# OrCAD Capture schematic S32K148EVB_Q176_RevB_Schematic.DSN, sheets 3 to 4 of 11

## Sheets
3 03. S32K148 MCUs: size E; company: Freescale Semiconductor; note: SCH-29642 PDF: SPF-29642
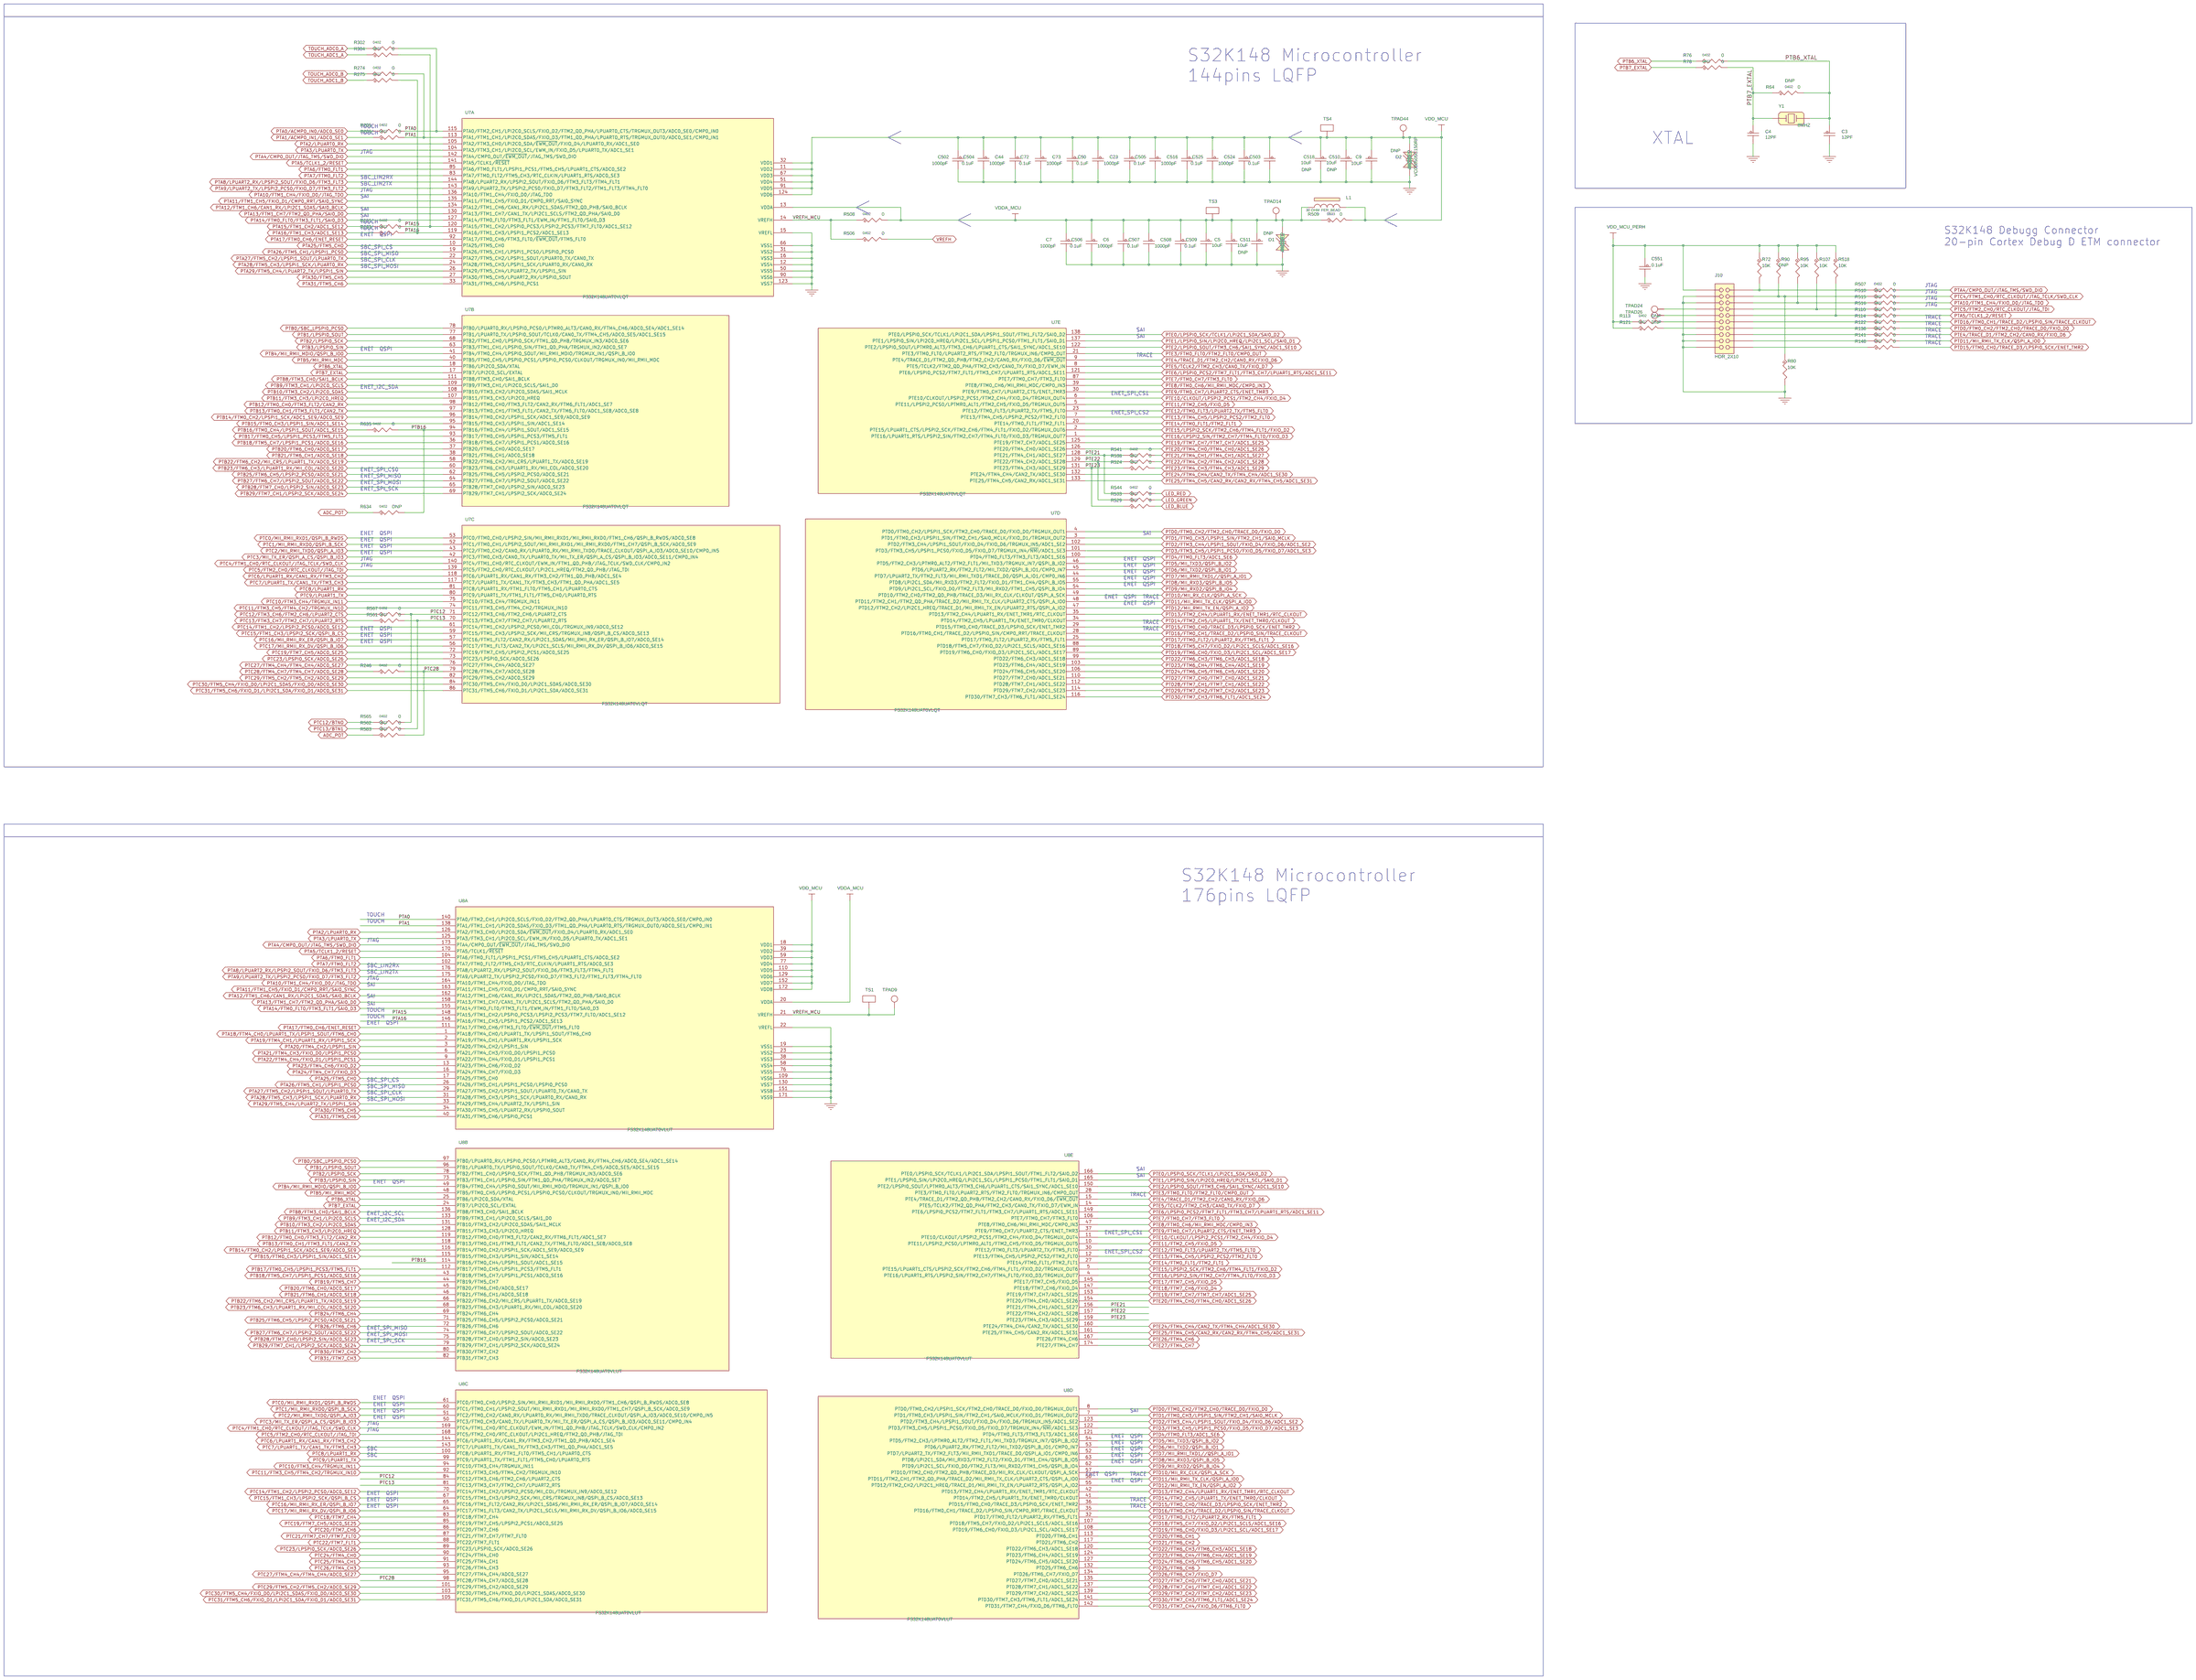
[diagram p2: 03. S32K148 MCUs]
4 04. MUXDMUX: size D; note: SCH-29642 PDF: SPF-29642
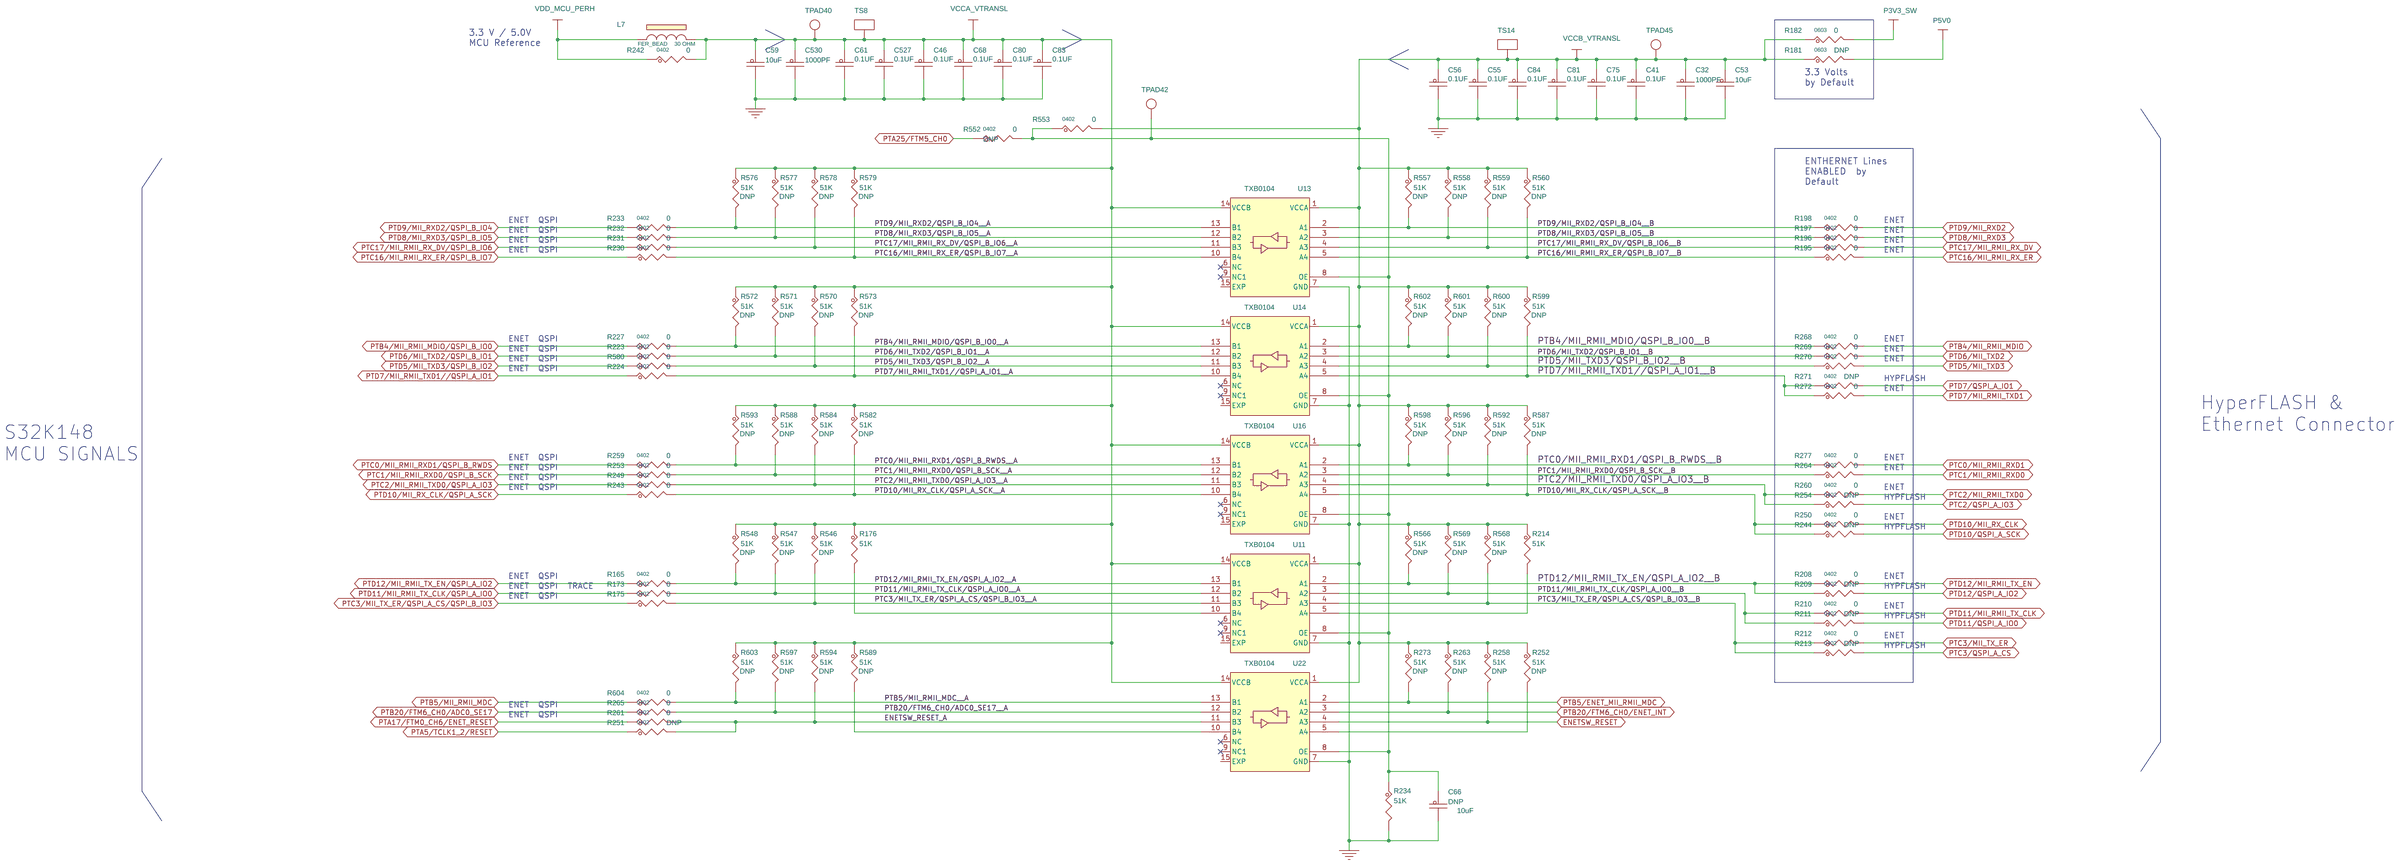
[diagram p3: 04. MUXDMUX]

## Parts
sheet 03. S32K148 MCUs
C3  12PF  [CC0402_25]
C4  12PF  [CC0402_25]
C5  10uF  [CC0603_OV]
C6  1000pF  [CC0402_25]
C7  1000pF  [CC0402_25]
C9  10UF  [CC0805_OV]
C23  1000pF  [CC0402_25]
C44  1000pF  [CC0402_25]
C50  0.1uF  [CC0402_25]
C72  0.1uF  [CC0402_25]
C73  1000pF  [CC0402_25]
C502  1000pF  [CC0402_25]
C503  0.1uF  [CC0402_25]
C504  0.1uF  [CC0402_25]
C505  0.1uF  [CC0402_25]
C506  0.1uF  [CC0402_25]
C507  0.1uF  [CC0402_25]
C508  1000pF  [CC0402_25]
C509  0.1uF  [CC0402_25]
C510  10uF  [CC0603_OV]
C511  10uF  [CC0603_OV]
C516  1000pF  [CC0402_25]
C518  10uF  [CC0603_OV]
C524  1000pF  [CC0402_25]
C525  0.1uF  [CC0402_25]
C551  0.1uF  [CC0402_25]
D1  VC080505C150RP  [0805]
D2  VC080505C150RP  [0805]
J10  HDR_2X10  [HDR210_FTSH_SM]
L1  30 OHM  [IND_0402]
R64  0  [RC0402_25]
R72  10K  [RC0603_OV]
R76  0  [RC0402_25]
R78  0  [RC0402_25]
R80  10K  [RC0603_OV]
R90  10K  [RC0603_OV]
R95  10K  [RC0603_OV]
R107  10K  [RC0603_OV]
R110  0  [RC0402_25]
R113  0  [RC0402_25]
R114  0  [RC0402_25]
R121  0  [RC0402_25]
R122  0  [RC0402_25]
R136  0  [RC0402_25]
R141  0  [RC0402_25]
R148  0  [RC0402_25]
R191  0  [RC0402_25]
R193  0  [RC0402_25]
R205  0  [RC0402_25]
R206  0  [RC0402_25]
R246  0  [RC0402_25]
R274  0  [RC0402_25]
R275  0  [RC0402_25]
R302  0  [RC0402_25]
R304  0  [RC0402_25]
R506  0  [RC0402_25]
R507  0  [RC0402_25]
R508  0  [RC0402_25]
R509  0  [RC0603]
R510  0  [RC0402_25]
R515  0  [RC0402_25]
R516  0  [RC0402_25]
R518  10K  [RC0603_OV]
R524  0  [RC0402_25]
R529  0  [RC0402_25]
R533  0  [RC0402_25]
R538  0  [RC0402_25]
R541  0  [RC0402_25]
R544  0  [RC0402_25]
R561  0  [RC0402_25]
R562  0  [RC0402_25]
R565  0  [RC0402_25]
R567  0  [RC0402_25]
R583  0  [RC0402_25]
R634  0  [RC0402_25]
R635  0  [RC0402_25]
TPAD9  TPAD_030  [TPAD_030]
TPAD14  TPAD_030  [TPAD_030]
TPAD24  TPAD_030  [TPAD_030]
TPAD26  TPAD_030  [TPAD_030]
TPAD44  TPAD_030  [TPAD_030]
TS1  TESTLOOP  [testpoint_135_070mil]
TS3  TESTLOOP  [testpoint_135_070mil]
TS4  TESTLOOP  [testpoint_135_070mil]
U7  FS32K148UAT0VLQT  [LQFP144_0P5_20X20MM]  (sections A,B,C,D,E)
U8  FS32K148UAT0VLUT  [TQFP176]  (sections A,B,C,D,E)
Y1  8MHZ  [xtal2_3p3x2p6]
sheet 04. MUXDMUX
C32  1000PF  [CC0603_OV]
C41  0.1UF  [CC0603_OV]
C46  0.1UF  [CC0603_OV]
C53  10uF  [CC0603_OV]
C55  0.1UF  [CC0603_OV]
C56  0.1UF  [CC0603_OV]
C59  10uF  [CC0603_OV]
C61  0.1UF  [CC0603_OV]
C66  10uF  [CC0603_OV]
C68  0.1UF  [CC0603_OV]
C75  0.1UF  [CC0603_OV]
C80  0.1UF  [CC0603_OV]
C81  0.1UF  [CC0603_OV]
C83  0.1UF  [CC0603_OV]
C84  0.1UF  [CC0603_OV]
C527  0.1UF  [CC0603_OV]
C530  1000PF  [CC0603_OV]
L7  30 OHM  [IND_0402]
R165  0  [RC0402_25]
R173  0  [RC0402_25]
R175  0  [RC0402_25]
R176  51K  [RC0402_25]
R181  0  [RC0603]
R182  0  [RC0603]
R195  0  [RC0402_25]
R196  0  [RC0402_25]
R197  0  [RC0402_25]
R198  0  [RC0402_25]
R208  0  [RC0402_25]
R209  0  [RC0402_25]
R210  0  [RC0402_25]
R211  0  [RC0402_25]
R212  0  [RC0402_25]
R213  0  [RC0402_25]
R214  51K  [RC0402_25]
R223  0  [RC0402_25]
R224  0  [RC0402_25]
R227  0  [RC0402_25]
R230  0  [RC0402_25]
R231  0  [RC0402_25]
R232  0  [RC0402_25]
R233  0  [RC0402_25]
R234  51K  [RC0402_25]
R242  0  [RC0402_25]
R243  0  [RC0402_25]
R244  0  [RC0402_25]
R249  0  [RC0402_25]
R250  0  [RC0402_25]
R251  0  [RC0402_25]
R252  51K  [RC0402_25]
R253  0  [RC0402_25]
R254  0  [RC0402_25]
R258  51K  [RC0402_25]
R259  0  [RC0402_25]
R260  0  [RC0402_25]
R261  0  [RC0402_25]
R263  51K  [RC0402_25]
R264  0  [RC0402_25]
R265  0  [RC0402_25]
R268  0  [RC0402_25]
R269  0  [RC0402_25]
R270  0  [RC0402_25]
R271  0  [RC0402_25]
R272  0  [RC0402_25]
R273  51K  [RC0402_25]
R277  0  [RC0402_25]
R546  51K  [RC0402_25]
R547  51K  [RC0402_25]
R548  51K  [RC0402_25]
R552  0  [RC0402_25]
R553  0  [RC0402_25]
R557  51K  [RC0402_25]
R558  51K  [RC0402_25]
R559  51K  [RC0402_25]
R560  51K  [RC0402_25]
R566  51K  [RC0402_25]
R568  51K  [RC0402_25]
R569  51K  [RC0402_25]
R570  51K  [RC0402_25]
R571  51K  [RC0402_25]
R572  51K  [RC0402_25]
R573  51K  [RC0402_25]
R576  51K  [RC0402_25]
R577  51K  [RC0402_25]
R578  51K  [RC0402_25]
R579  51K  [RC0402_25]
R580  0  [RC0402_25]
R582  51K  [RC0402_25]
R584  51K  [RC0402_25]
R587  51K  [RC0402_25]
R588  51K  [RC0402_25]
R589  51K  [RC0402_25]
R592  51K  [RC0402_25]
R593  51K  [RC0402_25]
R594  51K  [RC0402_25]
R596  51K  [RC0402_25]
R597  51K  [RC0402_25]
R598  51K  [RC0402_25]
R599  51K  [RC0402_25]
R600  51K  [RC0402_25]
R601  51K  [RC0402_25]
R602  51K  [RC0402_25]
R603  51K  [RC0402_25]
R604  0  [RC0402_25]
TPAD40  TPAD_030  [TPAD_030]
TPAD42  TPAD_030  [TPAD_030]
TPAD45  TPAD_030  [TPAD_030]
TS8  TESTLOOP  [testpoint_135_070mil]
TS14  TESTLOOP  [testpoint_135_070mil]
U11  TXB0104  [qfn14_rgy]
U13  TXB0104  [qfn14_rgy]
U14  TXB0104  [qfn14_rgy]
U16  TXB0104  [qfn14_rgy]
U22  TXB0104  [qfn14_rgy]

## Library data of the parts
C3 C4 = CAP_NP: CAP CER 12PF 50V 5% C0G 0402; AGILE_PN: 150-75680; CAD_APPROVED: Yes; FPLIST: CC0402_25,CC0402_HD,0402_CC; HEIGHT: 0.55MM; MFG_NAME01: NIC COMPONENTS CORP; MFG_PN01: NMC0402NPO120J50TRPF; ROHS: Yes; Tolerance: 5%; VOLTAGE: 50V
C5 = CAP_NP: CAP CER 10uF 25V 20% X5R 0603; AGILE_PN: 150-79272; CAD_APPROVED: Yes; FPLIST: CC0603_OV,CC0603,0603_CC; HEIGHT: 1MM; MFG_NAME01: Murata; MFG_PN01: GRM188R61E106MA73D; ROHS: Yes; TOL: 10%; Tolerance: 20%; VOLTAGE: 25V
C6 C7 C23 C44 C73 C502 C508 C516 C524 = CAP_NP: CAP CER 1000pF 50V 10% X7R AEC-Q200 0402; AGILE_PN: 150-79040; CAD_APPROVED: Yes; FPLIST: CC0402_25,CC0402_HD,0402_CC; HEIGHT: 0.55MM; MFG_NAME01: MURATA; MFG_PN01: GCM155R71H102KA37D; ROHS: Yes; Tolerance: 10%; VOLTAGE: 50V
C9 = CAP_NP: CAP CER 10UF 10V 10% X7R 0805; AGILE_PN: 150-78501; CAD_APPROVED: Yes; FPLIST: CC0603_OV,CC0603,0603_CC; HEIGHT: 1.4MM; MFG_NAME01: Murata; MFG_PN01: GRM21BR71A106KE51L; ROHS: Yes; Tolerance: 10%; VOLTAGE: 10V
C50 C72 C503-C507 C509 C525 C551 = CAP_NP: CAP CER 0.1uF 16V 10% X7R AEC-Q200 0402; AGILE_PN: 150-79025; CAD_APPROVED: Yes; FPLIST: CC0402_25,CC0402_HD,0402_CC; HEIGHT: 0.55MM; MFG_NAME01: MURATA; MFG_PN01: GCM155R71C104KA55D; ROHS: Yes
C510 C511 C518 = CAP_NP: CAP CER 10uF 25V 20% X5R 0603; AGILE_PN: 150-79272; ASSY_OPT: DNP; CAD_APPROVED: Yes; FPLIST: CC0603_OV,CC0603,0603_CC; HEIGHT: 1MM; MFG_NAME01: Murata; MFG_PN01: GRM188R61E106MA73D; ROHS: Yes; TOL: 10%; Tolerance: 20%; VOLTAGE: 25V
D1 D2 = TRANZORB_BIDIR_AA: DIODE TVS 5.6V 0.3J 18V 0805; AGILE_PN: 480-75537; ASSY_OPT: DNP; CAD_APPROVED: Yes; HEIGHT: 1.02MM; MFG_NAME01: AVX; ROHS: Yes
J10 = CONN_HDR_10X2: HDR 2X10 SMT 50MIL SP 251H AU; AGILE_PN: 211-78962; CAD_APPROVED: Yes; HEIGHT: 6.35MM; MFG_NAME01: SAMTEC; MFG_PN01: FTSH-110-01-L-DV-K; ROHS: Yes
L1 L7 = INDUCTOR_FERRITE: IND FER BEAD 30 OHM@100MHZ 2.2A 25% 0402; AGILE_PN: 180-77768; CAD_APPROVED: Yes; FPLIST: IND_0402,0402_CC; HEIGHT: 0.55MM; MFG_NAME01: Murata; MFG_PN01: BLM15PD300SN1D; PART_TYPE: FERRITE\BEAD; ROHS: Yes; Tolerance: 25%; _DESC: FER_BEAD
R64 R113 R121 R209 R211 R213 R244 R251 R254 R271 R552 R634 = RES: RES MF ZERO OHM 1/16W -- AEC-Q200 0402; AGILE_PN: 470-80742; ASSY_OPT: DNP; CAD_APPROVED: Yes; FPLIST: RC0402_25,RC0402_HD,0402_CC; HEIGHT: 0.45 MM; MFG_NAME01: VISHAY INTERTECHNOLOGY; MFG_PN01: CRCW04020000Z0ED; PCKG: 0402; ROHS: Yes
R72 R80 R95 R107 R518 = RES: RES MF 10K 1/10W 0.1% AEC-Q200 0603; AGILE_PN: 470-80764; CAD_APPROVED: Yes; FPLIST: RC0603_OV,RC0603,0603_CC; HEIGHT: 0.55MM; MFG_NAME01: Vishay Intertechnology; MFG_PN01: TNPW060310K0BEEN; ROHS: Yes; Tolerance: 0.1%
R76 R78 R110 R114 R122 R136 R141 R148 R165 R173 R175 R191 R193 R195-R198 R205 R206 R208 R210 R212 R223 R224 R227 R230-R233 R242 R243 R246 R249 R250 R253 R259-R261 R264 R265 R268-R270 R272 R274 R275 R277 R302 R304 R506-R508 R510 R515 R516 R524 R529 R533 R538 R541 R544 R553 R561 R562 R565 R567 R580 R583 R604 R635 = RES: RES MF ZERO OHM 1/16W -- AEC-Q200 0402; AGILE_PN: 470-80742; CAD_APPROVED: Yes; FPLIST: RC0402_25,RC0402_HD,0402_CC; HEIGHT: 0.45 MM; MFG_NAME01: VISHAY INTERTECHNOLOGY; MFG_PN01: CRCW04020000Z0ED; PCKG: 0402; ROHS: Yes
R90 = RES: RES MF 10K 1/10W 0.1% AEC-Q200 0603; AGILE_PN: 470-80764; ASSY_OPT: DNP; CAD_APPROVED: Yes; FPLIST: RC0603_OV,RC0603,0603_CC; HEIGHT: 0.55MM; MFG_NAME01: Vishay Intertechnology; MFG_PN01: TNPW060310K0BEEN; ROHS: Yes; Tolerance: 0.1%
R182 R509 = RES: RES MF ZERO OHM 1/10W -- AEC-Q200 0603; AGILE_PN: 470-75407; CAD_APPROVED: Yes; FPLIST: RC0603_OV,RC0603,R603-X2,0603_CC; HEIGHT: 0.6MM; MFG_NAME01: PANASONIC; MFG_PN01: ERJ-3GEY0R00V; PCKG: 0603; ROHS: Yes; Tolerance: 1%
TPAD9 TPAD14 TPAD24 TPAD26 TPAD40 TPAD42 TPAD44 TPAD45 = TestLoop: TEST POINT PAD 30MIL DIA SMT, NO PART TO ORDER; AGILE_PN: 211-76642; CAD_APPROVED: Yes; HEIGHT: 0.1MM; MFG_NAME01: NOTACOMPONENT; MFG_PN01: NOTACOMPONENT; ROHS: Yes
TS1 TS3 TS4 TS8 TS14 = TEST_POINT_4: TEST POINT PAD SIZE 3.4MM X 1.8MM SMT; AGILE_PN: 211-75906; CAD_APPROVED: Yes; HEIGHT: 1.53 MM; MFG_NAME01: KEYSTONE ELECTRONICS; MFG_PN01: 5015; PRIORITY_PN: 922-00014; ROHS: Yes
U7 = S32K1XX_LQFP_144P: IC MCU 2M FLASH 2.7-5.5V 112MHZ LQFP144; AGILE_PN: TMP-WF-28630; ASSY_OPT: DNP; CAD_APPROVED: Yes; HEIGHT: 1.6MM; MFG_NAME01: NXP SEMICONDUCTORS; MFG_PN01: PS32K148UAT0VLQT; PRE_APN: 344-02229; ROHS: Yes; Temp_Range: -40C to 125C
U8 = S32K1XX_LQFP_176P: IC MCU 32MHZ FLASH 2.7-5.5V 112MHZ LQFP176; AGILE_PN: TMP-WF-28631; CAD_APPROVED: Yes; HEIGHT: 1.6MM; MFG_NAME01: NXP SEMICONDUCTORS; MFG_PN01: PS32K118UEX0MLUT; PRE_APN: 344-02230; ROHS: Yes; Temp_Range: -40C to 125C
Y1 = XTAL_CS10: XTAL 8MHZ 8pF AEC-Q200 SMD; AGILE_PN: 230-77981; CAD_APPROVED: Yes; HEIGHT: 1MM; MFG_NAME01: NDK; MFG_PN01: NX3225GD-8MHZ-STD-CRA-3; ROHS: Yes
C32 C530 = CAP_NP: CAP CER 1000PF 25V 5% C0G CC0603; AGILE_PN: 150-75193; CAD_APPROVED: Yes; FPLIST: CC0603_OV,CC0603,0603_CC; HEIGHT: 0.87MM; MFG_NAME01: KEMET; MFG_PN01: C0603C102J3GAC; ROHS: Yes; Tolerance: 5%; VOLTAGE: 25V
C41 C46 C55 C56 C61 C68 C75 C80 C81 C83 C84 C527 = CAP_NP: CAP CER 0.10UF 25V 10% X7R 0603; AGILE_PN: 150-75016; CAD_APPROVED: Yes; FPLIST: CC0603_OV,CC0603,0603_CC; HEIGHT: 0.97 MM; MFG_NAME01: KEMET; MFG_PN01: C0603C104K3RAC; ROHS: Yes; TOL: 10%; Tolerance: 10%; VOLTAGE: 25V
C53 C59 = CAP_NP: CAP CER 10uF 25V 20% X5R 0603; AGILE_PN: 150-79272; CAD_APPROVED: Yes; FPLIST: CC0603_OV,CC0603,0603_CC; HEIGHT: 1MM; MFG_NAME01: Murata; MFG_PN01: GRM188R61E106MA73D; ROHS: Yes; SIGNAL_MODEL: DEFAULT_CAPACITOR_1e+07pF_2_1; Tolerance: 20%; VOLTAGE: 25V
C66 = CAP_NP: CAP CER 10uF 25V 20% X5R 0603; AGILE_PN: 150-79272; ASSY_OPT: DNP; CAD_APPROVED: Yes; FPLIST: CC0603_OV,CC0603,0603_CC; HEIGHT: 1MM; MFG_NAME01: Murata; MFG_PN01: GRM188R61E106MA73D; ROHS: Yes; SIGNAL_MODEL: DEFAULT_CAPACITOR_1e+07pF_2_1; Tolerance: 20%; VOLTAGE: 25V
R176 R214 R234 = RES: RES MF 51K 1/16W 1% AEC-Q200 0402; AGILE_PN: 470-80733; CAD_APPROVED: Yes; FPLIST: RC0402_25,RC0402_HD,0402_CC; HEIGHT: 0.4MM; MFG_NAME01: VISHAY INTERTECHNOLOGY; MFG_PN01: CRCW040251K0FKED; ROHS: Yes; Tolerance: 1%
R181 = RES: RES MF ZERO OHM 1/10W -- AEC-Q200 0603; AGILE_PN: 470-75407; ASSY_OPT: DNP; CAD_APPROVED: Yes; FPLIST: RC0603_OV,RC0603,R603-X2,0603_CC; HEIGHT: 0.6MM; MFG_NAME01: PANASONIC; MFG_PN01: ERJ-3GEY0R00V; PCKG: 0603; ROHS: Yes; Tolerance: 1%
R252 R258 R263 R273 R546-R548 R557-R560 R566 R568-R573 R576-R579 R582 R584 R587-R589 R592-R594 R596-R603 = RES: RES MF 51K 1/16W 1% AEC-Q200 0402; AGILE_PN: 470-80733; ASSY_OPT: DNP; CAD_APPROVED: Yes; FPLIST: RC0402_25,RC0402_HD,0402_CC; HEIGHT: 0.4MM; MFG_NAME01: VISHAY INTERTECHNOLOGY; MFG_PN01: CRCW040251K0FKED; ROHS: Yes; Tolerance: 1%
U11 U13 U14 U16 U22 = TXB0104: IC VXLTR 4BIT BIDIRECTIONAL 1.2-3.6V/1.65-5.5V QFN14; AGILE_PN: 312-78758; CAD_APPROVED: Yes; HEIGHT: 1MM; MFG_NAME01: TEXAS INSTRUMENTS; MFG_PN01: TXB0104RGYRG4; ROHS: Yes

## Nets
GND: C3.2 C4.2 C5.2 C6.2 C7.2 C9.2 C23.2 C32.2 C41.2 C44.2 C46.2 C50.2 C53.2 C55.2 C56.2 C59.2 C61.2 C66.2 C68.2 C72.2 C73.2 C75.2 C80.2 C81.2 C83.2 C84.2 C502.2 C503.2 C504.2 C505.2 C506.2 C507.2 C508.2 C509.2 C510.2 C511.2 C516.2 C518.2 C524.2 C525.2 C527.2 C530.2 C551.2 D1.2(ANODE2) D2.2(ANODE2) J10.3 J10.5 J10.15 J10.17 J10.19 R80.2 R234.2 U7.12(VSS4) U7.15(VREFL) U7.16(VSS3) U7.31(VSS2) U7.50(VSS5) U7.66(VSS1) U7.90(VSS6) U7.123(VSS7) U8.19(VSS1) U8.22(VREFL) U8.23(VSS2) U8.38(VSS3) U8.58(VSS4) U8.76(VSS5) U8.109(VSS6) U8.130(VSS7) U8.151(VSS8) U8.171(VSS9) U11.7(GND) U13.7(GND) U14.7(GND) U16.7(GND) U22.7(GND) ; also on sheet 1 2 5 6 7 8 9 11
P3V3_SW: R182.2 ; also on sheet 1 2 5 6 7 11
P5V0: R181.2 ; also on sheet 1 2 6 9 11
VCCA_VTRANSL: C46.1 C59.1 C61.1 C68.1 C80.1 C83.1 C527.1 C530.1 L7.2 R176.1 R242.2 R546.1 R547.1 R548.1 R570.1 R571.1 R572.1 R573.1 R576.1 R577.1 R578.1 R579.1 R582.1 R584.1 R588.1 R589.1 R593.1 R594.1 R597.1 R603.1 TPAD40.1(Pin1) TS8.1 U11.14(VCCB) U13.14(VCCB) U14.14(VCCB) U16.14(VCCB) U22.14(VCCB)
VCCB_VTRANSL: C32.1 C41.1 C53.1 C55.1 C56.1 C75.1 C81.1 C84.1 R181.1 R182.1 R214.1 R252.1 R258.1 R263.1 R273.1 R553.2 R557.1 R558.1 R559.1 R560.1 R566.1 R568.1 R569.1 R587.1 R592.1 R596.1 R598.1 R599.1 R600.1 R601.1 R602.1 TPAD45.1(Pin1) TS14.1 U11.1(VCCA) U13.1(VCCA) U14.1(VCCA) U16.1(VCCA) U22.1(VCCA)
VDD_MCU: C9.1 C23.1 C44.1 C50.1 C72.1 C73.1 C502.1 C503.1 C504.1 C505.1 C510.1 C516.1 C518.1 C524.1 C525.1 D2.1(ANODE1) L1.1 R509.2 TPAD44.1(Pin1) TS4.1 U7.11(VDD2) U7.32(VDD1) U7.51(VDD4) U7.67(VDD3) U7.91(VDD5) U7.124(VDD6) U8.18(VDD1) U8.39(VDD2) U8.59(VDD3) U8.77(VDD4) U8.110(VDD5) U8.129(VDD6) U8.152(VDD7) U8.172(VDD8) ; also on sheet 2
VDD_MCU_PERH: C551.1 J10.1 L7.1 R72.1 R90.1 R95.1 R107.1 R113.1 R121.1 R242.1 R518.1 ; also on sheet 2 6 9 11
VDDA_MCU: C5.1 C6.1 C7.1 C506.1 C507.1 C508.1 C509.1 C511.1 D1.1(ANODE1) L1.2 R508.2 R509.1 TPAD14.1(Pin1) TS3.1 U7.13(VDDA) U8.20(VDDA)
ADC_POT: R583.1 R634.1 ; also on sheet 9
ENETSW_RESET: R258.2 U22.4(A3) ; also on sheet 6
ENETSW_RESET_A: R251.2 R261.2 R594.2 U22.11(B3)
EXP: U11.15(EXP) U13.15(EXP) U14.15(EXP) U16.15(EXP) U22.15(EXP)
LED_BLUE: R529.2 ; also on sheet 9
LED_GREEN: R533.2 ; also on sheet 9
LED_RED: R544.2 ; also on sheet 9
PTA0: R205.2 R302.2 U7.115(PTA0/FTM2_CH1/LPI2C0_SCLS/FXIO_D2/FTM2_QD_PHA/LPUART0_CTS/TRGMUX_OUT3/ADC0_SE0/CMP0_IN0) U8.140(PTA0/FTM2_CH1/LPI2C0_SCLS/FXIO_D2/FTM2_QD_PHA/LPUART0_CTS/TRGMUX_OUT3/ADC0_SE0/CMP0_IN0)
PTA0/ACMP0_IN0/ADC0_SE0: R205.1 ; also on sheet 11
PTA1: R206.2 R274.2 U7.113(PTA1/FTM1_CH1/LPI2C0_SDAS/FXIO_D3/FTM1_QD_PHA/LPUART0_RTS/TRGMUX_OUT0/ADC0_SE1/CMP0_IN1) U8.138(PTA1/FTM1_CH1/LPI2C0_SDAS/FXIO_D3/FTM1_QD_PHA/LPUART0_RTS/TRGMUX_OUT0/ADC0_SE1/CMP0_IN1)
PTA1/ACMP0_IN1/ADC0_SE1: R206.1 ; also on sheet 11
PTA2/LPUART0_RX: U7.105(PTA2/FTM3_CH0/LPI2C0_SDA/~{EWM_OUT}/FXIO_D4/LPUART0_RX/ADC1_SE0) U8.126(PTA2/FTM3_CH0/LPI2C0_SDA/~{EWM_OUT}/FXIO_D4/LPUART0_RX/ADC1_SE0) ; also on sheet 2 11
PTA3/LPUART0_TX: U7.104(PTA3/FTM3_CH1/LPI2C0_SCL/EWM_IN/FXIO_D5/LPUART0_TX/ADC1_SE1) U8.125(PTA3/FTM3_CH1/LPI2C0_SCL/EWM_IN/FXIO_D5/LPUART0_TX/ADC1_SE1) ; also on sheet 2 11
PTA4/CMP0_OUT/JTAG_TMS/SWD_DIO: R507.2 U7.142(PTA4/CMP0_OUT/~{EWM_OUT}/JTAG_TMS/SWD_DIO) U8.173(PTA4/CMP0_OUT/~{EWM_OUT}/JTAG_TMS/SWD_DIO) ; also on sheet 5
PTA5/TCLK1_2/RESET: R110.2 R251.1 U7.141(PTA5/TCLK1/~{RESET}) U8.170(PTA5/TCLK1/~{RESET}) ; also on sheet 2 5 11
PTA6/FTM0_FLT1: U7.85(PTA6/FTM0_FLT1/LPSPI1_PCS1/FTM5_CH5/LPUART1_CTS/ADC0_SE2) U8.104(PTA6/FTM0_FLT1/LPSPI1_PCS1/FTM5_CH5/LPUART1_CTS/ADC0_SE2) ; also on sheet 11
PTA7/FTM0_FLT2: U7.83(PTA7/FTM0_FLT2/FTM5_CH3/RTC_CLKIN/LPUART1_RTS/ADC0_SE3) U8.102(PTA7/FTM0_FLT2/FTM5_CH3/RTC_CLKIN/LPUART1_RTS/ADC0_SE3) ; also on sheet 11
PTA8/LPUART2_RX/LPSPI2_SOUT/FXIO_D6/FTM3_FLT3: U7.144(PTA8/LPUART2_RX/LPSPI2_SOUT/FXIO_D6/FTM3_FLT3/FTM4_FLT1) U8.176(PTA8/LPUART2_RX/LPSPI2_SOUT/FXIO_D6/FTM3_FLT3/FTM4_FLT1) ; also on sheet 2 11
PTA9/LPUART2_TX/LPSPI2_PCS0/FXIO_D7/FTM3_FLT2: U7.143(PTA9/LPUART2_TX/LPSPI2_PCS0/FXIO_D7/FTM3_FLT2/FTM1_FLT3/FTM4_FLT0) U8.175(PTA9/LPUART2_TX/LPSPI2_PCS0/FXIO_D7/FTM3_FLT2/FTM1_FLT3/FTM4_FLT0) ; also on sheet 2 11
PTA10/FTM1_CH4/FXIO_D0/JTAG_TDO: R515.2 U7.136(PTA10/FTM1_CH4/FXIO_D0/JTAG_TDO) U8.164(PTA10/FTM1_CH4/FXIO_D0/JTAG_TDO)
PTA11/FTM1_CH5/FXIO_D1/CMP0_RRT/SAI0_SYNC: U7.135(PTA11/FTM1_CH5/FXIO_D1/CMP0_RRT/SAI0_SYNC) U8.163(PTA11/FTM1_CH5/FXIO_D1/CMP0_RRT/SAI0_SYNC) ; also on sheet 1 11
PTA12/FTM1_CH6/CAN1_RX/LPI2C1_SDAS/SAI0_BCLK: U7.134(PTA12/FTM1_CH6/CAN1_RX/LPI2C1_SDAS/FTM2_QD_PHB/SAI0_BCLK) U8.162(PTA12/FTM1_CH6/CAN1_RX/LPI2C1_SDAS/FTM2_QD_PHB/SAI0_BCLK) ; also on sheet 1 11
PTA13/FTM1_CH7/FTM2_QD_PHA/SAI0_D0: U7.130(PTA13/FTM1_CH7/CAN1_TX/LPI2C1_SCLS/FTM2_QD_PHA/SAI0_D0) U8.158(PTA13/FTM1_CH7/CAN1_TX/LPI2C1_SCLS/FTM2_QD_PHA/SAI0_D0) ; also on sheet 1 11
PTA14/FTM0_FLT0/FTM3_FLT1/SAI0_D3: U7.127(PTA14/FTM0_FLT0/FTM3_FLT1/EWM_IN/FTM1_FLT0/SAI0_D3) U8.155(PTA14/FTM0_FLT0/FTM3_FLT1/EWM_IN/FTM1_FLT0/SAI0_D3) ; also on sheet 1 11
PTA15: R191.2 R304.2 U7.120(PTA15/FTM1_CH2/LPSPI0_PCS3/LPSPI2_PCS3/FTM7_FLT0/ADC1_SE12) U8.148(PTA15/FTM1_CH2/LPSPI0_PCS3/LPSPI2_PCS3/FTM7_FLT0/ADC1_SE12)
PTA15/FTM1_CH2/ADC1_SE12: R191.1 ; also on sheet 11
PTA16: R193.2 R275.2 U7.119(PTA16/FTM1_CH3/LPSPI1_PCS2/ADC1_SE13) U8.146(PTA16/FTM1_CH3/LPSPI1_PCS2/ADC1_SE13)
PTA16/FTM1_CH3/ADC1_SE13: R193.1 ; also on sheet 11
PTA17/FTM0_CH6/ENET_RESET: R261.1 U7.92(PTA17/FTM0_CH6/FTM3_FLT0/~{EWM_OUT}/FTM5_FLT0) U8.111(PTA17/FTM0_CH6/FTM3_FLT0/~{EWM_OUT}/FTM5_FLT0) ; also on sheet 11
PTA18/FTM4_CH0/LPUART1_TX/LPSPI1_SOUT/FTM6_CH0: U8.1(PTA18/FTM4_CH0/LPUART1_TX/LPSPI1_SOUT/FTM6_CH0) ; also on sheet 11
PTA19/FTM4_CH1/LPUART1_RX/LPSPI1_SCK: U8.2(PTA19/FTM4_CH1/LPUART1_RX/LPSPI1_SCK) ; also on sheet 11
PTA20/FTM4_CH2/LPSPI1_SIN: U8.3(PTA20/FTM4_CH2/LPSPI1_SIN) ; also on sheet 11
PTA21/FTM4_CH3/FXIO_D0/LPSPI1_PCS0: U8.6(PTA21/FTM4_CH3/FXIO_D0/LPSPI1_PCS0) ; also on sheet 11
PTA22/FTM4_CH4/FXIO_D1/LPSPI1_PCS1: U8.9(PTA22/FTM4_CH4/FXIO_D1/LPSPI1_PCS1) ; also on sheet 11
PTA23/FTM4_CH6/FXIO_D2: U8.13(PTA23/FTM4_CH6/FXIO_D2) ; also on sheet 11
PTA24/FTM4_CH7/FXIO_D3: U8.16(PTA24/FTM4_CH7/FXIO_D3) ; also on sheet 11
PTA25/FTM5_CH0: R552.1 U7.10(PTA25/FTM5_CH0) U8.17(PTA25/FTM5_CH0) ; also on sheet 11
PTA26/FTM5_CH1/LPSPI1_PCS0: U7.19(PTA26/FTM5_CH1/LPSPI1_PCS0/LPSPI0_PCS0) U8.26(PTA26/FTM5_CH1/LPSPI1_PCS0/LPSPI0_PCS0) ; also on sheet 2 11
PTA27/FTM5_CH2/LPSPI1_SOUT/LPUART0_TX: U7.22(PTA27/FTM5_CH2/LPSPI1_SOUT/LPUART0_TX/CAN0_TX) U8.29(PTA27/FTM5_CH2/LPSPI1_SOUT/LPUART0_TX/CAN0_TX) ; also on sheet 2 11
PTA28/FTM5_CH3/LPSPI1_SCK/LPUART0_RX: U7.24(PTA28/FTM5_CH3/LPSPI1_SCK/LPUART0_RX/CAN0_RX) U8.31(PTA28/FTM5_CH3/LPSPI1_SCK/LPUART0_RX/CAN0_RX) ; also on sheet 2 11
PTA29/FTM5_CH4/LPUART2_TX/LPSPI1_SIN: U7.26(PTA29/FTM5_CH4/LPUART2_TX/LPSPI1_SIN) U8.33(PTA29/FTM5_CH4/LPUART2_TX/LPSPI1_SIN) ; also on sheet 2 11
PTA30/FTM5_CH5: U7.27(PTA30/FTM5_CH5/LPUART2_RX/LPSPI0_SOUT) U8.34(PTA30/FTM5_CH5/LPUART2_RX/LPSPI0_SOUT) ; also on sheet 11
PTA31/FTM5_CH6: U7.33(PTA31/FTM5_CH6/LPSPI0_PCS1) U8.40(PTA31/FTM5_CH6/LPSPI0_PCS1) ; also on sheet 11
PTB0/SBC_LPSPI0_PCS0: U7.78(PTB0/LPUART0_RX/LPSPI0_PCS0/LPTMR0_ALT3/CAN0_RX/FTM4_CH6/ADC0_SE4/ADC1_SE14) U8.97(PTB0/LPUART0_RX/LPSPI0_PCS0/LPTMR0_ALT3/CAN0_RX/FTM4_CH6/ADC0_SE4/ADC1_SE14) ; also on sheet 11
PTB1/LPSPI0_SOUT: U7.77(PTB1/LPUART0_TX/LPSPI0_SOUT/TCLK0/CAN0_TX/FTM4_CH5/ADC0_SE5/ADC1_SE15) U8.96(PTB1/LPUART0_TX/LPSPI0_SOUT/TCLK0/CAN0_TX/FTM4_CH5/ADC0_SE5/ADC1_SE15) ; also on sheet 11
PTB2/LPSPI0_SCK: U7.68(PTB2/FTM1_CH0/LPSPI0_SCK/FTM1_QD_PHB/TRGMUX_IN3/ADC0_SE6) U8.78(PTB2/FTM1_CH0/LPSPI0_SCK/FTM1_QD_PHB/TRGMUX_IN3/ADC0_SE6) ; also on sheet 11
PTB3/LPSPI0_SIN: U7.63(PTB3/FTM1_CH1/LPSPI0_SIN/FTM1_QD_PHA/TRGMUX_IN2/ADC0_SE7) U8.73(PTB3/FTM1_CH1/LPSPI0_SIN/FTM1_QD_PHA/TRGMUX_IN2/ADC0_SE7) ; also on sheet 11
PTB4/MII_RMII_MDIO: R268.2 ; also on sheet 6
PTB4/MII_RMII_MDIO/QSPI_B_IO0: R227.1 U7.41(PTB4/FTM0_CH4/LPSPI0_SOUT/MII_RMII_MDIO/TRGMUX_IN1/QSPI_B_IO0) U8.49(PTB4/FTM0_CH4/LPSPI0_SOUT/MII_RMII_MDIO/TRGMUX_IN1/QSPI_B_IO0)
PTB4/MII_RMII_MDIO/QSPI_B_IO0__A: R227.2 R572.2 U14.13(B1)
PTB4/MII_RMII_MDIO/QSPI_B_IO0__B: R268.1 R602.2 U14.2(A1)
PTB5/ENET_MII_RMII_MDC: R273.2 U22.2(A1) ; also on sheet 6
PTB5/MII_RMII_MDC: R604.1 U7.40(PTB5/FTM0_CH5/LPSPI0_PCS1/LPSPI0_PCS0/CLKOUT/TRGMUX_IN0/MII_RMII_MDC) U8.48(PTB5/FTM0_CH5/LPSPI0_PCS1/LPSPI0_PCS0/CLKOUT/TRGMUX_IN0/MII_RMII_MDC)
PTB5/MII_RMII_MDC__A: R603.2 R604.2 U22.13(B1)
PTB6_XTAL: C3.1 R64.2 R76.1 R76.2 U7.18(PTB6/LPI2C0_SDA/XTAL) U8.25(PTB6/LPI2C0_SDA/XTAL) Y1.2
PTB7_EXTAL: C4.1 R64.1 R78.1 R78.2 U7.17(PTB7/LPI2C0_SCL/EXTAL) U8.24(PTB7/LPI2C0_SCL/EXTAL) Y1.1
PTB8/FTM3_CH0/SAI1_BCLK: U7.111(PTB8/FTM3_CH0/SAI1_BCLK) U8.136(PTB8/FTM3_CH0/SAI1_BCLK) ; also on sheet 1 11
PTB9/FTM3_CH1/LPI2C0_SCLS: U7.109(PTB9/FTM3_CH1/LPI2C0_SCLS/SAI1_D0) U8.133(PTB9/FTM3_CH1/LPI2C0_SCLS/SAI1_D0) ; also on sheet 1 6 11
PTB10/FTM3_CH2/LPI2C0_SDAS: U7.108(PTB10/FTM3_CH2/LPI2C0_SDAS/SAI1_MCLK) U8.131(PTB10/FTM3_CH2/LPI2C0_SDAS/SAI1_MCLK) ; also on sheet 1 6 11
PTB11/FTM3_CH3/LPI2C0_HREQ: U7.107(PTB11/FTM3_CH3/LPI2C0_HREQ) U8.128(PTB11/FTM3_CH3/LPI2C0_HREQ) ; also on sheet 11
PTB12/FTM0_CH0/FTM3_FLT2/CAN2_RX: U7.98(PTB12/FTM0_CH0/FTM3_FLT2/CAN2_RX/FTM6_FLT1/ADC1_SE7) U8.119(PTB12/FTM0_CH0/FTM3_FLT2/CAN2_RX/FTM6_FLT1/ADC1_SE7) ; also on sheet 11
PTB13/FTM0_CH1/FTM3_FLT1/CAN2_TX: U7.97(PTB13/FTM0_CH1/FTM3_FLT1/CAN2_TX/FTM6_FLT0/ADC1_SE8/ADC0_SE8) U8.118(PTB13/FTM0_CH1/FTM3_FLT1/CAN2_TX/FTM6_FLT0/ADC1_SE8/ADC0_SE8) ; also on sheet 11
PTB14/FTM0_CH2/LPSPI1_SCK/ADC1_SE9/ADC0_SE9: U7.96(PTB14/FTM0_CH2/LPSPI1_SCK/ADC1_SE9/ADC0_SE9) U8.116(PTB14/FTM0_CH2/LPSPI1_SCK/ADC1_SE9/ADC0_SE9) ; also on sheet 11
PTB15/FTM0_CH3/LPSPI1_SIN/ADC1_SE14: U7.95(PTB15/FTM0_CH3/LPSPI1_SIN/ADC1_SE14) U8.115(PTB15/FTM0_CH3/LPSPI1_SIN/ADC1_SE14) ; also on sheet 11
PTB16: R634.2 R635.2 U7.94(PTB16/FTM0_CH4/LPSPI1_SOUT/ADC1_SE15) U8.114(PTB16/FTM0_CH4/LPSPI1_SOUT/ADC1_SE15)
PTB16/FTM0_CH4/LPSPI1_SOUT/ADC1_SE15: R635.1 ; also on sheet 11
PTB17/FTM0_CH5/LPSPI1_PCS3/FTM5_FLT1: U7.93(PTB17/FTM0_CH5/LPSPI1_PCS3/FTM5_FLT1) U8.112(PTB17/FTM0_CH5/LPSPI1_PCS3/FTM5_FLT1) ; also on sheet 11
PTB18/FTM5_CH7/LPSPI1_PCS1/ADC0_SE16: U7.36(PTB18/FTM5_CH7/LPSPI1_PCS1/ADC0_SE16) U8.43(PTB18/FTM5_CH7/LPSPI1_PCS1/ADC0_SE16) ; also on sheet 11
PTB19/FTM5_CH7: U8.44(PTB19/FTM5_CH7) ; also on sheet 11
PTB20/FTM6_CH0/ADC0_SE17: R265.1 U7.37(PTB20/FTM6_CH0/ADC0_SE17) U8.45(PTB20/FTM6_CH0/ADC0_SE17) ; also on sheet 11
PTB20/FTM6_CH0/ADC0_SE17__A: R265.2 R597.2 U22.12(B2)
PTB20/FTM6_CH0/ENET_INT: R263.2 U22.3(A2) ; also on sheet 6
PTB21/FTM6_CH1/ADC0_SE18: U7.38(PTB21/FTM6_CH1/ADC0_SE18) U8.46(PTB21/FTM6_CH1/ADC0_SE18) ; also on sheet 11
PTB22/FTM6_CH2/MII_CRS/LPUART1_TX/ADC0_SE19: U7.58(PTB22/FTM6_CH2/MII_CRS/LPUART1_TX/ADC0_SE19) U8.66(PTB22/FTM6_CH2/MII_CRS/LPUART1_TX/ADC0_SE19) ; also on sheet 11
PTB23/FTM6_CH3/LPUART1_RX/MII_COL/ADC0_SE20: U7.60(PTB23/FTM6_CH3/LPUART1_RX/MII_COL/ADC0_SE20) U8.68(PTB23/FTM6_CH3/LPUART1_RX/MII_COL/ADC0_SE20) ; also on sheet 11
PTB24/FTM6_CH4: U8.69(PTB24/FTM6_CH4) ; also on sheet 11
PTB25/FTM6_CH5/LPSPI2_PCS0/ADC0_SE21: U7.62(PTB25/FTM6_CH5/LPSPI2_PCS0/ADC0_SE21) U8.71(PTB25/FTM6_CH5/LPSPI2_PCS0/ADC0_SE21) ; also on sheet 6 11
PTB26/FTM6_CH6: U8.72(PTB26/FTM6_CH6) ; also on sheet 11
PTB27/FTM6_CH7/LPSPI2_SOUT/ADC0_SE22: U7.64(PTB27/FTM6_CH7/LPSPI2_SOUT/ADC0_SE22) U8.74(PTB27/FTM6_CH7/LPSPI2_SOUT/ADC0_SE22) ; also on sheet 6 11
PTB28/FTM7_CH0/LPSPI2_SIN/ADC0_SE23: U7.65(PTB28/FTM7_CH0/LPSPI2_SIN/ADC0_SE23) U8.75(PTB28/FTM7_CH0/LPSPI2_SIN/ADC0_SE23) ; also on sheet 6 11
PTB29/FTM7_CH1/LPSPI2_SCK/ADC0_SE24: U7.69(PTB29/FTM7_CH1/LPSPI2_SCK/ADC0_SE24) U8.79(PTB29/FTM7_CH1/LPSPI2_SCK/ADC0_SE24) ; also on sheet 6 11
PTB30/FTM7_CH2: U8.80(PTB30/FTM7_CH2) ; also on sheet 11
PTB31/FTM7_CH3: U8.82(PTB31/FTM7_CH3) ; also on sheet 11
PTC0/MII_RMII_RXD1: R277.2 ; also on sheet 6
PTC0/MII_RMII_RXD1/QSPI_B_RWDS: R259.1 U7.53(PTC0/FTM0_CH0/LPSPI2_SIN/MII_RMII_RXD1/MII_RMII_RXD0/FTM1_CH6/QSPI_B_RWDS/ADC0_SE8) U8.61(PTC0/FTM0_CH0/LPSPI2_SIN/MII_RMII_RXD1/MII_RMII_RXD0/FTM1_CH6/QSPI_B_RWDS/ADC0_SE8)
PTC0/MII_RMII_RXD1/QSPI_B_RWDS__A: R259.2 R593.2 U16.13(B1)
PTC0/MII_RMII_RXD1/QSPI_B_RWDS__B: R277.1 R598.2 U16.2(A1)
PTC1/MII_RMII_RXD0: R264.2 ; also on sheet 6
PTC1/MII_RMII_RXD0/QSPI_B_SCK: R253.1 U7.52(PTC1/FTM0_CH1/LPSPI2_SOUT/MII_RMII_RXD1/MII_RMII_RXD0/FTM1_CH7/QSPI_B_SCK/ADC0_SE9) U8.60(PTC1/FTM0_CH1/LPSPI2_SOUT/MII_RMII_RXD1/MII_RMII_RXD0/FTM1_CH7/QSPI_B_SCK/ADC0_SE9)
PTC1/MII_RMII_RXD0/QSPI_B_SCK__A: R253.2 R588.2 U16.12(B2)
PTC1/MII_RMII_RXD0/QSPI_B_SCK__B: R264.1 R596.2 U16.3(A2)
PTC2/MII_RMII_TXD0: R260.2 ; also on sheet 6
PTC2/MII_RMII_TXD0/QSPI_A_IO3: R249.1 U7.43(PTC2/FTM0_CH2/CAN0_RX/LPUART0_RX/MII_RMII_TXD0/TRACE_CLKOUT/QSPI_A_IO3/ADC0_SE10/CMP0_IN5) U8.51(PTC2/FTM0_CH2/CAN0_RX/LPUART0_RX/MII_RMII_TXD0/TRACE_CLKOUT/QSPI_A_IO3/ADC0_SE10/CMP0_IN5)
PTC2/MII_RMII_TXD0/QSPI_A_IO3__A: R249.2 R584.2 U16.11(B3)
PTC2/MII_RMII_TXD0/QSPI_A_IO3__B: R254.1 R260.1 R592.2 U16.4(A3)
PTC2/QSPI_A_IO3: R254.2 ; also on sheet 7
PTC3/MII_TX_ER: R212.2 ; also on sheet 6
PTC3/MII_TX_ER/QSPI_A_CS/QSPI_B_IO3: R175.1 U7.42(PTC3/FTM0_CH3/CAN0_TX/LPUART0_TX/MII_TX_ER/QSPI_A_CS/QSPI_B_IO3/ADC0_SE11/CMP0_IN4) U8.50(PTC3/FTM0_CH3/CAN0_TX/LPUART0_TX/MII_TX_ER/QSPI_A_CS/QSPI_B_IO3/ADC0_SE11/CMP0_IN4)
PTC3/MII_TX_ER/QSPI_A_CS/QSPI_B_IO3__A: R175.2 R546.2 U11.11(B3)
PTC3/MII_TX_ER/QSPI_A_CS/QSPI_B_IO3__B: R212.1 R213.1 R568.2 U11.4(A3)
PTC3/QSPI_A_CS: R213.2 ; also on sheet 7
PTC4/FTM1_CH0/RTC_CLKOUT/JTAG_TCLK/SWD_CLK: R510.2 U7.140(PTC4/FTM1_CH0/RTC_CLKOUT/EWM_IN/FTM1_QD_PHB/JTAG_TCLK/SWD_CLK/CMP0_IN2) U8.169(PTC4/FTM1_CH0/RTC_CLKOUT/EWM_IN/FTM1_QD_PHB/JTAG_TCLK/SWD_CLK/CMP0_IN2) ; also on sheet 5
PTC5/FTM2_CH0/RTC_CLKOUT/JTAG_TDI: R516.2 U7.139(PTC5/FTM2_CH0/RTC_CLKOUT/LPI2C1_HREQ/FTM2_QD_PHB/JTAG_TDI) U8.168(PTC5/FTM2_CH0/RTC_CLKOUT/LPI2C1_HREQ/FTM2_QD_PHB/JTAG_TDI)
PTC6/LPUART1_RX/CAN1_RX/FTM3_CH2: U7.118(PTC6/LPUART1_RX/CAN1_RX/FTM3_CH2/FTM1_QD_PHB/ADC1_SE4) U8.144(PTC6/LPUART1_RX/CAN1_RX/FTM3_CH2/FTM1_QD_PHB/ADC1_SE4) ; also on sheet 5 11
PTC7/LPUART1_TX/CAN1_TX/FTM3_CH3: U7.117(PTC7/LPUART1_TX/CAN1_TX/FTM3_CH3/FTM1_QD_PHA/ADC1_SE5) U8.143(PTC7/LPUART1_TX/CAN1_TX/FTM3_CH3/FTM1_QD_PHA/ADC1_SE5) ; also on sheet 5 11
PTC8/LPUART1_RX: U7.81(PTC8/LPUART1_RX/FTM1_FLT0/FTM5_CH1/LPUART0_CTS) U8.100(PTC8/LPUART1_RX/FTM1_FLT0/FTM5_CH1/LPUART0_CTS) ; also on sheet 5 11
PTC9/LPUART1_TX: U7.80(PTC9/LPUART1_TX/FTM1_FLT1/FTM5_CH0/LPUART0_RTS) U8.99(PTC9/LPUART1_TX/FTM1_FLT1/FTM5_CH0/LPUART0_RTS) ; also on sheet 5 11
PTC10/FTM3_CH4/TRGMUX_IN11: U7.75(PTC10/FTM3_CH4/TRGMUX_IN11) U8.94(PTC10/FTM3_CH4/TRGMUX_IN11) ; also on sheet 11
PTC11/FTM3_CH5/FTM4_CH2/TRGMUX_IN10: U7.74(PTC11/FTM3_CH5/FTM4_CH2/TRGMUX_IN10) U8.92(PTC11/FTM3_CH5/FTM4_CH2/TRGMUX_IN10) ; also on sheet 11
PTC12: R565.2 R567.2 U7.71(PTC12/FTM3_CH6/FTM2_CH6/LPUART2_CTS) U8.84(PTC12/FTM3_CH6/FTM2_CH6/LPUART2_CTS)
PTC12/BTN0: R565.1 ; also on sheet 9
PTC12/FTM3_CH6/FTM2_CH6/LPUART2_CTS: R567.1 ; also on sheet 11
PTC13: R561.2 R562.2 U7.70(PTC13/FTM3_CH7/FTM2_CH7/LPUART2_RTS) U8.81(PTC13/FTM3_CH7/FTM2_CH7/LPUART2_RTS)
PTC13/BTN1: R562.1 ; also on sheet 9
PTC13/FTM3_CH7/FTM2_CH7/LPUART2_RTS: R561.1 ; also on sheet 11
PTC14/FTM1_CH2/LPSPI2_PCS0/ADC0_SE12: U7.61(PTC14/FTM1_CH2/LPSPI2_PCS0/MII_COL/TRGMUX_IN9/ADC0_SE12) U8.70(PTC14/FTM1_CH2/LPSPI2_PCS0/MII_COL/TRGMUX_IN9/ADC0_SE12) ; also on sheet 11
PTC15/FTM1_CH3/LPSPI2_SCK/QSPI_B_CS: U7.59(PTC15/FTM1_CH3/LPSPI2_SCK/MII_CRS/TRGMUX_IN8/QSPI_B_CS/ADC0_SE13) U8.67(PTC15/FTM1_CH3/LPSPI2_SCK/MII_CRS/TRGMUX_IN8/QSPI_B_CS/ADC0_SE13) ; also on sheet 11
PTC16/MII_RMII_RX_ER: R195.2 ; also on sheet 6
PTC16/MII_RMII_RX_ER/QSPI_B_IO7: R230.1 U7.57(PTC16/FTM1_FLT2/CAN2_RX/LPI2C1_SDAS/MII_RMII_RX_ER/QSPI_B_IO7/ADC0_SE14) U8.65(PTC16/FTM1_FLT2/CAN2_RX/LPI2C1_SDAS/MII_RMII_RX_ER/QSPI_B_IO7/ADC0_SE14)
PTC16/MII_RMII_RX_ER/QSPI_B_IO7__A: R230.2 R579.2 U13.10(B4)
PTC16/MII_RMII_RX_ER/QSPI_B_IO7__B: R195.1 R560.2 U13.5(A4)
PTC17/MII_RMII_RX_DV: R196.2 ; also on sheet 6
PTC17/MII_RMII_RX_DV/QSPI_B_IO6: R231.1 U7.56(PTC17/FTM1_FLT3/CAN2_TX/LPI2C1_SCLS/MII_RMII_RX_DV/QSPI_B_IO6/ADC0_SE15) U8.64(PTC17/FTM1_FLT3/CAN2_TX/LPI2C1_SCLS/MII_RMII_RX_DV/QSPI_B_IO6/ADC0_SE15)
PTC17/MII_RMII_RX_DV/QSPI_B_IO6__A: R231.2 R578.2 U13.11(B3)
PTC17/MII_RMII_RX_DV/QSPI_B_IO6__B: R196.1 R559.2 U13.4(A3)
PTC18/FTM7_CH4: U8.83(PTC18/FTM7_CH4) ; also on sheet 11
PTC19/FTM7_CH5/ADC0_SE25: U7.72(PTC19/FTM7_CH5/LPSPI2_PCS1/ADC0_SE25) U8.85(PTC19/FTM7_CH5/LPSPI2_PCS1/ADC0_SE25) ; also on sheet 11
PTC20/FTM7_CH6: U8.86(PTC20/FTM7_CH6) ; also on sheet 11
PTC21/FTM7_CH7/FTM7_FLT0: U8.87(PTC21/FTM7_CH7/FTM7_FLT0) ; also on sheet 11
PTC22/FTM7_FLT1: U8.88(PTC22/FTM7_FLT1) ; also on sheet 11
PTC23/LPSPI0_SCK/ADC0_SE26: U7.73(PTC23/LPSPI0_SCK/ADC0_SE26) U8.89(PTC23/LPSPI0_SCK/ADC0_SE26) ; also on sheet 11
PTC24/FTM4_CH0: U8.90(PTC24/FTM4_CH0) ; also on sheet 11
PTC25/FTM4_CH1: U8.91(PTC25/FTM4_CH1) ; also on sheet 11
PTC26/FTM4_CH3: U8.93(PTC26/FTM4_CH3) ; also on sheet 11
PTC27/FTM4_CH4/FTM4_CH4/ADC0_SE27: U7.76(PTC27/FTM4_CH4/ADC0_SE27) U8.95(PTC27/FTM4_CH4/ADC0_SE27) ; also on sheet 11
PTC28: R246.2 R583.2 U7.79(PTC28/FTM4_CH7/ADC0_SE28) U8.98(PTC28/FTM4_CH7/ADC0_SE28)
PTC28/FTM4_CH7/FTM4_CH7/ADC0_SE28: R246.1 ; also on sheet 11
PTC29/FTM5_CH2/FTM5_CH2/ADC0_SE29: U7.82(PTC29/FTM5_CH2/ADC0_SE29) U8.101(PTC29/FTM5_CH2/ADC0_SE29) ; also on sheet 11
PTC30/FTM5_CH4/FXIO_D0/LPI2C1_SDAS/FXIO_D0/ADC0_SE30: U7.84(PTC30/FTM5_CH4/FXIO_D0/LPI2C1_SDAS/ADC0_SE30) U8.103(PTC30/FTM5_CH4/FXIO_D0/LPI2C1_SDAS/ADC0_SE30) ; also on sheet 1 11
PTC31/FTM5_CH6/FXIO_D1/LPI2C1_SDA/FXIO_D1/ADC0_SE31: U7.86(PTC31/FTM5_CH6/FXIO_D1/LPI2C1_SDA/ADC0_SE31) U8.105(PTC31/FTM5_CH6/FXIO_D1/LPI2C1_SDA/ADC0_SE31) ; also on sheet 1 11
PTD0/FTM0_CH2/FTM2_CH0/TRACE_D0/FXIO_D0: R122.2 U7.4(PTD0/FTM0_CH2/LPSPI1_SCK/FTM2_CH0/TRACE_D0/FXIO_D0/TRGMUX_OUT1) U8.8(PTD0/FTM0_CH2/LPSPI1_SCK/FTM2_CH0/TRACE_D0/FXIO_D0/TRGMUX_OUT1) ; also on sheet 11
PTD1/FTM0_CH3/LPSPI1_SIN/FTM2_CH1/SAI0_MCLK: U7.3(PTD1/FTM0_CH3/LPSPI1_SIN/FTM2_CH1/SAI0_MCLK/FXIO_D1/TRGMUX_OUT2) U8.7(PTD1/FTM0_CH3/LPSPI1_SIN/FTM2_CH1/SAI0_MCLK/FXIO_D1/TRGMUX_OUT2) ; also on sheet 1 11
PTD2/FTM3_CH4/LPSPI1_SOUT/FXIO_D4/FXIO_D6/ADC1_SE2: U7.102(PTD2/FTM3_CH4/LPSPI1_SOUT/FXIO_D4/FXIO_D6/TRGMUX_IN5/ADC1_SE2) U8.123(PTD2/FTM3_CH4/LPSPI1_SOUT/FXIO_D4/FXIO_D6/TRGMUX_IN5/ADC1_SE2) ; also on sheet 11
PTD3/FTM3_CH5/LPSPI1_PCS0/FXIO_D5/FXIO_D7/ADC1_SE3: U7.101(PTD3/FTM3_CH5/LPSPI1_PCS0/FXIO_D5/FXIO_D7/TRGMUX_IN4/~{NMI}/ADC1_SE3) U8.122(PTD3/FTM3_CH5/LPSPI1_PCS0/FXIO_D5/FXIO_D7/TRGMUX_IN4/~{NMI}/ADC1_SE3) ; also on sheet 11
PTD4/FTM0_FLT3/ADC1_SE6: U7.100(PTD4/FTM0_FLT3/FTM3_FLT3/ADC1_SE6) U8.121(PTD4/FTM0_FLT3/FTM3_FLT3/ADC1_SE6) ; also on sheet 11
PTD5/MII_TXD3: R270.2 ; also on sheet 6
PTD5/MII_TXD3/QSPI_B_IO2: R580.1 U7.46(PTD5/FTM2_CH3/LPTMR0_ALT2/FTM2_FLT1/MII_TXD3/TRGMUX_IN7/QSPI_B_IO2) U8.54(PTD5/FTM2_CH3/LPTMR0_ALT2/FTM2_FLT1/MII_TXD3/TRGMUX_IN7/QSPI_B_IO2)
PTD5/MII_TXD3/QSPI_B_IO2__A: R570.2 R580.2 U14.11(B3)
PTD5/MII_TXD3/QSPI_B_IO2__B: R270.1 R600.2 U14.4(A3)
PTD6/MII_TXD2: R269.2 ; also on sheet 6
PTD6/MII_TXD2/QSPI_B_IO1: R223.1 U7.45(PTD6/LPUART2_RX/FTM2_FLT2/MII_TXD2/QSPI_B_IO1/CMP0_IN7) U8.53(PTD6/LPUART2_RX/FTM2_FLT2/MII_TXD2/QSPI_B_IO1/CMP0_IN7)
PTD6/MII_TXD2/QSPI_B_IO1__A: R223.2 R571.2 U14.12(B2)
PTD6/MII_TXD2/QSPI_B_IO1__B: R269.1 R601.2 U14.3(A2)
PTD7/MII_RMII_TXD1: R272.2 ; also on sheet 6
PTD7/MII_RMII_TXD1//QSPI_A_IO1: R224.1 U7.44(PTD7/LPUART2_TX/FTM2_FLT3/MII_RMII_TXD1/TRACE_D0/QSPI_A_IO1/CMP0_IN6) U8.52(PTD7/LPUART2_TX/FTM2_FLT3/MII_RMII_TXD1/TRACE_D0/QSPI_A_IO1/CMP0_IN6)
PTD7/MII_RMII_TXD1//QSPI_A_IO1__A: R224.2 R573.2 U14.10(B4)
PTD7/MII_RMII_TXD1//QSPI_A_IO1__B: R271.1 R272.1 R599.2 U14.5(A4)
PTD7/QSPI_A_IO1: R271.2 ; also on sheet 7
PTD8/MII_RXD3: R197.2 ; also on sheet 6
PTD8/MII_RXD3/QSPI_B_IO5: R232.1 U7.55(PTD8/LPI2C1_SDA/MII_RXD3/FTM2_FLT2/FXIO_D1/FTM1_CH4/QSPI_B_IO5) U8.63(PTD8/LPI2C1_SDA/MII_RXD3/FTM2_FLT2/FXIO_D1/FTM1_CH4/QSPI_B_IO5)
PTD8/MII_RXD3/QSPI_B_IO5__A: R232.2 R577.2 U13.12(B2)
PTD8/MII_RXD3/QSPI_B_IO5__B: R197.1 R558.2 U13.3(A2)
PTD9/MII_RXD2: R198.2 ; also on sheet 6
PTD9/MII_RXD2/QSPI_B_IO4: R233.1 U7.54(PTD9/LPI2C1_SCL/FXIO_D0/FTM2_FLT3/MII_RXD2/FTM1_CH5/QSPI_B_IO4) U8.62(PTD9/LPI2C1_SCL/FXIO_D0/FTM2_FLT3/MII_RXD2/FTM1_CH5/QSPI_B_IO4)
PTD9/MII_RXD2/QSPI_B_IO4__A: R233.2 R576.2 U13.13(B1)
PTD9/MII_RXD2/QSPI_B_IO4__B: R198.1 R557.2 U13.2(A1)
PTD10/MII_RX_CLK: R250.2 ; also on sheet 6
PTD10/MII_RX_CLK/QSPI_A_SCK: R243.1 U7.49(PTD10/FTM2_CH0/FTM2_QD_PHB/TRACE_D3/MII_RX_CLK/CLKOUT/QSPI_A_SCK) U8.57(PTD10/FTM2_CH0/FTM2_QD_PHB/TRACE_D3/MII_RX_CLK/CLKOUT/QSPI_A_SCK)
PTD10/MII_RX_CLK/QSPI_A_SCK__A: R243.2 R582.2 U16.10(B4)
PTD10/MII_RX_CLK/QSPI_A_SCK__B: R244.1 R250.1 R587.2 U16.5(A4)
PTD10/QSPI_A_SCK: R244.2 ; also on sheet 7
PTD11/MII_RMII_TX_CLK: R210.2 ; also on sheet 6
PTD11/MII_RMII_TX_CLK/QSPI_A_IO0: R141.2 R173.1 U7.48(PTD11/FTM2_CH1/FTM2_QD_PHA/TRACE_D2/MII_RMII_TX_CLK/LPUART2_CTS/QSPI_A_IO0) U8.56(PTD11/FTM2_CH1/FTM2_QD_PHA/TRACE_D2/MII_RMII_TX_CLK/LPUART2_CTS/QSPI_A_IO0)
PTD11/MII_RMII_TX_CLK/QSPI_A_IO0__A: R173.2 R547.2 U11.12(B2)
PTD11/MII_RMII_TX_CLK/QSPI_A_IO0__B: R210.1 R211.1 R569.2 U11.3(A2)
PTD11/QSPI_A_IO0: R211.2 ; also on sheet 7
PTD12/MII_RMII_TX_EN: R208.2 ; also on sheet 6
PTD12/MII_RMII_TX_EN/QSPI_A_IO2: R165.1 U7.47(PTD12/FTM2_CH2/LPI2C1_HREQ/TRACE_D1/MII_RMII_TX_EN/LPUART2_RTS/QSPI_A_IO2) U8.55(PTD12/FTM2_CH2/LPI2C1_HREQ/TRACE_D1/MII_RMII_TX_EN/LPUART2_RTS/QSPI_A_IO2)
PTD12/MII_RMII_TX_EN/QSPI_A_IO2__A: R165.2 R548.2 U11.13(B1)
PTD12/MII_RMII_TX_EN/QSPI_A_IO2__B: R208.1 R209.1 R566.2 U11.2(A1)
PTD12/QSPI_A_IO2: R209.2 ; also on sheet 7
PTD13/FTM2_CH4/LPUART1_RX/ENET_TMR1/RTC_CLKOUT: U7.35(PTD13/FTM2_CH4/LPUART1_RX/ENET_TMR1/RTC_CLKOUT) U8.42(PTD13/FTM2_CH4/LPUART1_RX/ENET_TMR1/RTC_CLKOUT) ; also on sheet 1 11
PTD14/FTM2_CH5/LPUART1_TX/ENET_TMR0/CLKOUT: U7.34(PTD14/FTM2_CH5/LPUART1_TX/ENET_TMR0/CLKOUT) U8.41(PTD14/FTM2_CH5/LPUART1_TX/ENET_TMR0/CLKOUT) ; also on sheet 1 11
PTD15/FTM0_CH0/TRACE_D3/LPSPI0_SCK/ENET_TMR2: R148.2 U7.29(PTD15/FTM0_CH0/TRACE_D3/LPSPI0_SCK/ENET_TMR2) U8.36(PTD15/FTM0_CH0/TRACE_D3/LPSPI0_SCK/ENET_TMR2) ; also on sheet 1 11
PTD16/FTM0_CH1/TRACE_D2/LPSPI0_SIN/TRACE_CLKOUT: R114.2 U7.28(PTD16/FTM0_CH1/TRACE_D2/LPSPI0_SIN/CMP0_RRT/TRACE_CLKOUT) U8.35(PTD16/FTM0_CH1/TRACE_D2/LPSPI0_SIN/CMP0_RRT/TRACE_CLKOUT) ; also on sheet 11
PTD17/FTM0_FLT2/LPUART2_RX/FTM5_FLT1: U7.25(PTD17/FTM0_FLT2/LPUART2_RX/FTM5_FLT1) U8.32(PTD17/FTM0_FLT2/LPUART2_RX/FTM5_FLT1) ; also on sheet 11
PTD18/FTM5_CH7/FXIO_D2/LPI2C1_SCLS/ADC1_SE16: U7.88(PTD18/FTM5_CH7/FXIO_D2/LPI2C1_SCLS/ADC1_SE16) U8.107(PTD18/FTM5_CH7/FXIO_D2/LPI2C1_SCLS/ADC1_SE16) ; also on sheet 1 11
PTD19/FTM6_CH0/FXIO_D3/LPI2C1_SCL/ADC1_SE17: U7.89(PTD19/FTM6_CH0/FXIO_D3/LPI2C1_SCL/ADC1_SE17) U8.108(PTD19/FTM6_CH0/FXIO_D3/LPI2C1_SCL/ADC1_SE17) ; also on sheet 1 11
PTD20/FTM6_CH1: U8.113(PTD20/FTM6_CH1) ; also on sheet 11
PTD21/FTM6_CH2: U8.117(PTD21/FTM6_CH2) ; also on sheet 11
PTD22/FTM6_CH3/FTM6_CH3/ADC1_SE18: U7.99(PTD22/FTM6_CH3/ADC1_SE18) U8.120(PTD22/FTM6_CH3/ADC1_SE18) ; also on sheet 11
PTD23/FTM6_CH4/FTM6_CH4/ADC1_SE19: U7.103(PTD23/FTM6_CH4/ADC1_SE19) U8.124(PTD23/FTM6_CH4/ADC1_SE19) ; also on sheet 11
PTD24/FTM6_CH5/FTM6_CH5/ADC1_SE20: U7.106(PTD24/FTM6_CH5/ADC1_SE20) U8.127(PTD24/FTM6_CH5/ADC1_SE20) ; also on sheet 11
PTD25/FTM6_CH6: U8.132(PTD25/FTM6_CH6) ; also on sheet 11
PTD26/FTM6_CH7/FXIO_D7: U8.134(PTD26/FTM6_CH7/FXIO_D7) ; also on sheet 11
PTD27/FTM7_CH0/FTM7_CH0/ADC1_SE21: U7.110(PTD27/FTM7_CH0/ADC1_SE21) U8.135(PTD27/FTM7_CH0/ADC1_SE21) ; also on sheet 11
PTD28/FTM7_CH1/FTM7_CH1/ADC1_SE22: U7.112(PTD28/FTM7_CH1/ADC1_SE22) U8.137(PTD28/FTM7_CH1/ADC1_SE22) ; also on sheet 11
PTD29/FTM7_CH2/FTM7_CH2/ADC1_SE23: U7.114(PTD29/FTM7_CH2/ADC1_SE23) U8.139(PTD29/FTM7_CH2/ADC1_SE23) ; also on sheet 6 11
PTD30/FTM7_CH3/FTM6_FLT1/ADC1_SE24: U7.116(PTD30/FTM7_CH3/FTM6_FLT1/ADC1_SE24) U8.141(PTD30/FTM7_CH3/FTM6_FLT1/ADC1_SE24) ; also on sheet 11
PTD31/FTM7_CH4/FXIO_D6/FTM6_FLT0: U8.142(PTD31/FTM7_CH4/FXIO_D6/FTM6_FLT0) ; also on sheet 11
PTE0/LPSPI0_SCK/TCLK1/LPI2C1_SDA/SAI0_D2: U7.138(PTE0/LPSPI0_SCK/TCLK1/LPI2C1_SDA/LPSPI1_SOUT/FTM1_FLT2/SAI0_D2) U8.166(PTE0/LPSPI0_SCK/TCLK1/LPI2C1_SDA/LPSPI1_SOUT/FTM1_FLT2/SAI0_D2) ; also on sheet 1 11
PTE1/LPSPI0_SIN/LPI2C0_HREQ/LPI2C1_SCL/SAI0_D1: U7.137(PTE1/LPSPI0_SIN/LPI2C0_HREQ/LPI2C1_SCL/LPSPI1_PCS0/FTM1_FLT1/SAI0_D1) U8.165(PTE1/LPSPI0_SIN/LPI2C0_HREQ/LPI2C1_SCL/LPSPI1_PCS0/FTM1_FLT1/SAI0_D1) ; also on sheet 1 11
PTE2/LPSPI0_SOUT/FTM3_CH6/SAI1_SYNC/ADC1_SE10: U7.122(PTE2/LPSPI0_SOUT/LPTMR0_ALT3/FTM3_CH6/LPUART1_CTS/SAI1_SYNC/ADC1_SE10) U8.150(PTE2/LPSPI0_SOUT/LPTMR0_ALT3/FTM3_CH6/LPUART1_CTS/SAI1_SYNC/ADC1_SE10) ; also on sheet 1 11
PTE3/FTM0_FLT0/FTM2_FLT0/CMP0_OUT: U7.21(PTE3/FTM0_FLT0/LPUART2_RTS/FTM2_FLT0/TRGMUX_IN6/CMP0_OUT) U8.28(PTE3/FTM0_FLT0/LPUART2_RTS/FTM2_FLT0/TRGMUX_IN6/CMP0_OUT) ; also on sheet 11
PTE4/TRACE_D1/FTM2_CH2/CAN0_RX/FXIO_D6: R136.2 U7.9(PTE4/TRACE_D1/FTM2_QD_PHB/FTM2_CH2/CAN0_RX/FXIO_D6/~{EWM_OUT}) U8.15(PTE4/TRACE_D1/FTM2_QD_PHB/FTM2_CH2/CAN0_RX/FXIO_D6/~{EWM_OUT}) ; also on sheet 2
PTE5/TCLK2/FTM2_CH3/CAN0_TX/FXIO_D7: U7.8(PTE5/TCLK2/FTM2_QD_PHA/FTM2_CH3/CAN0_TX/FXIO_D7/EWM_IN) U8.14(PTE5/TCLK2/FTM2_QD_PHA/FTM2_CH3/CAN0_TX/FXIO_D7/EWM_IN) ; also on sheet 2
PTE6/LPSPI0_PCS2/FTM7_FLT1/FTM3_CH7/LPUART1_RTS/ADC1_SE11: U7.121(PTE6/LPSPI0_PCS2/FTM7_FLT1/FTM3_CH7/LPUART1_RTS/ADC1_SE11) U8.149(PTE6/LPSPI0_PCS2/FTM7_FLT1/FTM3_CH7/LPUART1_RTS/ADC1_SE11) ; also on sheet 11
PTE7/FTM0_CH7/FTM3_FLT0: U7.87(PTE7/FTM0_CH7/FTM3_FLT0) U8.106(PTE7/FTM0_CH7/FTM3_FLT0) ; also on sheet 11
PTE8/FTM0_CH6/MII_RMII_MDC/CMP0_IN3: U7.39(PTE8/FTM0_CH6/MII_RMII_MDC/CMP0_IN3) U8.47(PTE8/FTM0_CH6/MII_RMII_MDC/CMP0_IN3) ; also on sheet 11
PTE9/FTM0_CH7/LPUART2_CTS/ENET_TMR3: U7.30(PTE9/FTM0_CH7/LPUART2_CTS/ENET_TMR3) U8.37(PTE9/FTM0_CH7/LPUART2_CTS/ENET_TMR3) ; also on sheet 1 11
PTE10/CLKOUT/LPSPI2_PCS1/FTM2_CH4/FXIO_D4: U7.6(PTE10/CLKOUT/LPSPI2_PCS1/FTM2_CH4/FXIO_D4/TRGMUX_OUT4) U8.11(PTE10/CLKOUT/LPSPI2_PCS1/FTM2_CH4/FXIO_D4/TRGMUX_OUT4) ; also on sheet 1 6 11
PTE11/FTM2_CH5/FXIO_D5: U7.5(PTE11/LPSPI2_PCS0/LPTMR0_ALT1/FTM2_CH5/FXIO_D5/TRGMUX_OUT5) U8.10(PTE11/LPSPI2_PCS0/LPTMR0_ALT1/FTM2_CH5/FXIO_D5/TRGMUX_OUT5) ; also on sheet 1 11
PTE12/FTM0_FLT3/LPUART2_TX/FTM5_FLT0: U7.23(PTE12/FTM0_FLT3/LPUART2_TX/FTM5_FLT0) U8.30(PTE12/FTM0_FLT3/LPUART2_TX/FTM5_FLT0) ; also on sheet 11
PTE13/FTM4_CH5/LPSPI2_PCS2/FTM2_FLT0: U7.7(PTE13/FTM4_CH5/LPSPI2_PCS2/FTM2_FLT0) U8.12(PTE13/FTM4_CH5/LPSPI2_PCS2/FTM2_FLT0) ; also on sheet 6 11
PTE14/FTM0_FLT1/FTM2_FLT1: U7.20(PTE14/FTM0_FLT1/FTM2_FLT1) U8.27(PTE14/FTM0_FLT1/FTM2_FLT1) ; also on sheet 11
PTE15/LPSPI2_SCK/FTM2_CH6/FTM4_FLT1/FXIO_D2: U7.2(PTE15/LPUART1_CTS/LPSPI2_SCK/FTM2_CH6/FTM4_FLT1/FXIO_D2/TRGMUX_OUT6) U8.5(PTE15/LPUART1_CTS/LPSPI2_SCK/FTM2_CH6/FTM4_FLT1/FXIO_D2/TRGMUX_OUT6) ; also on sheet 1 11
PTE16/LPSPI2_SIN/FTM2_CH7/FTM4_FLT0/FXIO_D3: U7.1(PTE16/LPUART1_RTS/LPSPI2_SIN/FTM2_CH7/FTM4_FLT0/FXIO_D3/TRGMUX_OUT7) U8.4(PTE16/LPUART1_RTS/LPSPI2_SIN/FTM2_CH7/FTM4_FLT0/FXIO_D3/TRGMUX_OUT7) ; also on sheet 1 11
PTE17/FTM7_CH5/FXIO_D5: U8.145(PTE17/FTM7_CH5/FXIO_D5) ; also on sheet 11
PTE18/FTM7_CH6/FXIO_D4: U8.147(PTE18/FTM7_CH6/FXIO_D4) ; also on sheet 11
PTE19/FTM7_CH7/FTM7_CH7/ADC1_SE25: U7.125(PTE19/FTM7_CH7/ADC1_SE25) U8.153(PTE19/FTM7_CH7/ADC1_SE25) ; also on sheet 2 11
PTE20/FTM4_CH0/FTM4_CH0/ADC1_SE26: U7.126(PTE20/FTM4_CH0/ADC1_SE26) U8.154(PTE20/FTM4_CH0/ADC1_SE26) ; also on sheet 2 11
PTE21: R541.1 R544.1 U7.128(PTE21/FTM4_CH1/ADC1_SE27) U8.156(PTE21/FTM4_CH1/ADC1_SE27)
PTE21/FTM4_CH1/FTM4_CH1/ADC1_SE27: R541.2 ; also on sheet 11
PTE22: R533.1 R538.1 U7.129(PTE22/FTM4_CH2/ADC1_SE28) U8.157(PTE22/FTM4_CH2/ADC1_SE28)
PTE22/FTM4_CH2/FTM4_CH2/ADC1_SE28: R538.2 ; also on sheet 11
PTE23: R524.1 R529.1 U7.131(PTE23/FTM4_CH3/ADC1_SE29) U8.159(PTE23/FTM4_CH3/ADC1_SE29)
PTE23/FTM4_CH3/FTM4_CH3/ADC1_SE29: R524.2 ; also on sheet 11
PTE24/FTM4_CH4/CAN2_TX/FTM4_CH4/ADC1_SE30: U7.132(PTE24/FTM4_CH4/CAN2_TX/ADC1_SE30) U8.160(PTE24/FTM4_CH4/CAN2_TX/ADC1_SE30) ; also on sheet 11
PTE25/FTM4_CH5/CAN2_RX/CAN2_RX/FTM4_CH5/ADC1_SE31: U7.133(PTE25/FTM4_CH5/CAN2_RX/ADC1_SE31) U8.161(PTE25/FTM4_CH5/CAN2_RX/ADC1_SE31) ; also on sheet 11
PTE26/FTM4_CH6: U8.167(PTE26/FTM4_CH6) ; also on sheet 11
PTE27/FTM4_CH7: U8.174(PTE27/FTM4_CH7) ; also on sheet 11
TOUCH_ADC0_A: R302.1 ; also on sheet 8
TOUCH_ADC0_B: R274.1 ; also on sheet 8
TOUCH_ADC1_A: R304.1 ; also on sheet 8
TOUCH_ADC1_B: R275.1 ; also on sheet 8
VREFH: R506.2 ; also on sheet 11
VREFH_MCU: R506.1 R508.1 TPAD9.1(Pin1) TS1.1 U7.14(VREFH) U8.21(VREFH)
N16823835: J10.6 R95.2 R515.1
N16823837: J10.8 R107.2 R516.1
N16823868: J10.2 R72.2 R507.1
N16823904: J10.10 R110.1 R518.2
N16823906: J10.4 R80.1 R90.2 R510.1
N17104821: C66.1 R234.1 R552.2 R553.1 TPAD42.1(Pin1) U11.8(OE) U13.8(OE) U14.8(OE) U16.8(OE) U22.8(OE)
N17121372: J10.20 R148.1
N17121375: J10.18 R141.1
N17121420: J10.12 R114.1
N17121423: J10.14 R122.1
N17121426: J10.16 R136.1
N17122140: J10.11 R113.2
N17122143: J10.13 R121.2
N17258367: J10.7 TPAD24.1(Pin1)
N17258370: J10.9 TPAD26.1(Pin1)
N20564874: R252.2 U22.5(A4)
N20580503: R214.2 U11.5(A4)
N20743373: R589.2 U22.10(B4)
N20743518: R176.2 U11.10(B4)

Not connected (* = marked no-connect by the designer): U11 6(NC)* 9(NC1)*; U13 6(NC)* 9(NC1)*; U14 6(NC)* 9(NC1)*; U16 6(NC)* 9(NC1)*; U22 6(NC)* 9(NC1)*

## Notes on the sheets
sheet 3
- S32K148 Microcontroller
  144pins LQFP
- TOUCH
- TOUCH
- XTAL
- JTAG
- SBC_LIN2RX
- SBC_LIN2TX
- JTAG
- SAI
- SAI
- SAI
- TOUCH
- TOUCH
- S32K148 Debugg Connector
  20-pin Cortex Debug D ETM connector
- ENET
- QSPI
- SBC_SPI_CS
- SBC_SPI_MISO
- SBC_SPI_CLK
- SBC_SPI_MOSI
- JTAG
- JTAG
- JTAG
- JTAG
- TRACE
- SAI
- TRACE
- TRACE
- SAI
- TRACE
- TRACE
- ENET
- QSPI
- TRACE
- ENET_I2C_SDA
- ENET_SPI_CS1
- ENET_SPI_CS2
- ENET_SPI_CS0
- ENET_SPI_MISO
- ENET_SPI_MOSI
- ENET_SPI_SCK
- ENET
- ENET
- QSPI
- QSPI
- SAI
- ENET
- QSPI
- ENET
- QSPI
- JTAG
- ENET
- QSPI
- JTAG
- ENET
- QSPI
- ENET
- ENET
- QSPI
- QSPI
- ENET
- QSPI
- ENET
- QSPI
- TRACE
- ENET
- QSPI
- TRACE
- ENET
- QSPI
- TRACE
- ENET
- QSPI
- ENET
- QSPI
- S32K148 Microcontroller
  176pins LQFP
- TOUCH
- TOUCH
- JTAG
- SBC_LIN2RX
- SBC_LIN2TX
- JTAG
- SAI
- SAI
- SAI
- TOUCH
- TOUCH
- ENET
- QSPI
- SBC_SPI_CS
- SBC_SPI_MISO
- SBC_SPI_CLK
- SBC_SPI_MOSI
- SAI
- SAI
- ENET
- QSPI
- TRACE
- ENET_I2C_SCL
- ENET_I2C_SDA
- ENET_SPI_CS1
- ENET_SPI_CS2
- ENET_SPI_MISO
- ENET_SPI_MOSI
- ENET_SPI_SCK
- ENET
- QSPI
- ENET
- ENET
- QSPI
- QSPI
- SAI
- ENET
- QSPI
- JTAG
- JTAG
- ENET
- QSPI
- SBC
- ENET
- ENET
- QSPI
- QSPI
- SBC
- ENET
- QSPI
- ENET
- QSPI
- ENET
- QSPI
- TRACE
- ENET
- QSPI
- ENET
- QSPI
- ENET
- QSPI
- TRACE
- ENET
- QSPI
- TRACE
sheet 4
- 3.3 V / 5.0V
  MCU Reference
- 3.3 Volts
  by Default
- ENTHERNET Lines
  ENABLED  by
  Default
- ENET
- QSPI
- ENET
- ENET
- ENET
- QSPI
- QSPI
- ENET
- ENET
- ENET
- QSPI
- ENET
- ENET
- QSPI
- ENET
- ENET
- QSPI
- ENET
- ENET
- ENET
- QSPI
- QSPI
- ENET
- HYPFLASH
- ENET
- HyperFLASH &
  Ethernet Connector
- S32K148
  MCU SIGNALS
- ENET
- QSPI
- ENET
- ENET
- QSPI
- ENET
- ENET
- QSPI
- ENET
- QSPI
- ENET
- HYPFLASH
- ENET
- HYPFLASH
- ENET
- QSPI
- ENET
- ENET
- QSPI
- TRACE
- HYPFLASH
- ENET
- QSPI
- ENET
- HYPFLASH
- ENET
- HYPFLASH
- ENET
- QSPI
- ENET
- QSPI
